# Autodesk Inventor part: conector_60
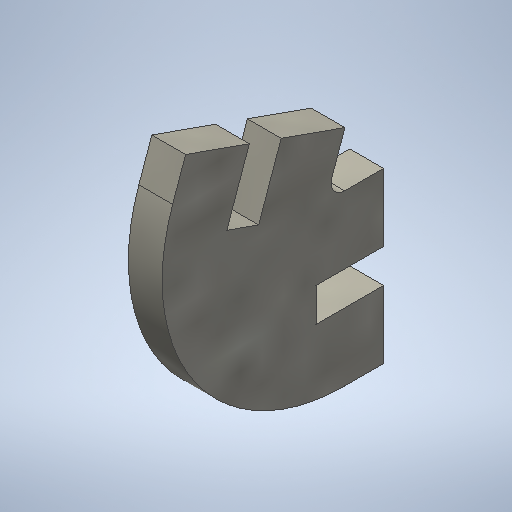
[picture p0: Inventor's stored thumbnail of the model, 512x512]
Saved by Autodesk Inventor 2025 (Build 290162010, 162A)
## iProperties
Created: 2025-02
Part Number: conector_60
Material: Paper
Document SubType Name: Modeling
Designer: BennF
Density: 0.93 g/cm^3
Appearance: Cardboard - Chipboard
Author: BennF
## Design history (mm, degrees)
sketch "Sketch2"
  geometry: L1 (0, -1)-(2.879, -1); L2 (2.879, -1)-(2.879, -6); L3 (2.879, -6)-(-2.121, -6); L4 (-2.121, -6)-(-2.121, -8.5); L5 (-2.121, -8.5)-(2.879, -8.5); L6 (2.879, -8.5)-(2.879, -13.5); L7 (2.879, -13.5)-(0, -13.5); L8 (-0.943, 0.333)-(0.017, 3.047); L9 (0.017, 3.047)-(-4.697, 4.714); L10 (-4.697, 4.714)-(-6.364, 0); L11 (-6.364, 0)-(-8.721, 0.833); L12 (-8.721, 0.833)-(-7.054, 5.547); L13 (-7.054, 5.547)-(-11.768, 7.214); L14 (-11.768, 7.214)-(-12.728, 4.5); L15 (-6.364, 0)-(-2.121, -6); A1 r 1 centre (0, 0) between (-0.943, 0.333) and (0, -1); A2 r 13.5 centre (0, 0) between (-12.728, 4.5) and (0, -13.5); 1 further point
  constraints: 30 end point, 10 perpendicular, 5 equal length, 4 point on circle, 4 point on line, 4 tangent, 2 centre point, 2 coincident, 1 horizontal
  dimensions: "d0" = 70.5288 deg angle of L1 L8 (= con_angle_3); "d1" = 2.5 distance of L10.end L11.end (= thickness); "d2" = 5 distance of L11.end L12.end (= slot_depth); "d3" = 5 distance of L12.end L13.end (= slot_dis_1); "d4" = 1 radius of A1; "d7" = 6 vertical distance of L3.end L10.end (computed from slot_depth)
extrude "Extrusion1" new body sketch "Sketch2" distance "d5" = 2.5 (= thickness); taper "d6" = 0 deg
sketch "laser"
  geometry: L1 (-4.714, -4.697)-(0, -6.364) reference; L2 (0, -6.364)-(-0.833, -8.721) reference; L3 (-0.833, -8.721)-(-5.547, -7.054) reference; L4 (-5.547, -7.054)-(-7.214, -11.768) reference; L5 (-7.214, -11.768)-(-4.5, -12.728) reference; L6 (13.5, 0)-(13.5, 2.879) reference; L7 (13.5, 2.879)-(8.5, 2.879) reference; L8 (8.5, 2.879)-(8.5, -2.121) reference; L9 (8.5, -2.121)-(6, -2.121) reference; L10 (6, -2.121)-(6, 2.879) reference; L11 (6, 2.879)-(1, 2.879) reference; L12 (1, 2.879)-(1, 0) reference; L13 (-0.333, -0.943)-(-3.047, 0.017) reference; L14 (-3.047, 0.017)-(-4.714, -4.697) reference; A1 r 13.5 centre (0, 0) between (-4.5, -12.728) and (13.5, 0) reference; A2 r 1 centre (0, 0) between (-0.333, -0.943) and (1, 0) reference; 1 further point
  node "Projected Loop1"
body "Solid1"
other parameters: "thickness" = 2.5 [user parameter; used in 2 equation terms], "clearence" = -0.5 [user parameter], "slot_depth" = 5 [user parameter; used in 2 equation terms], "slot_dis_1" = 5 [user parameter; used in 1 equation term], "slot_dis_2" = 12 [user parameter], "slot_clearenece" = 3 [user parameter], "con_angle_1" = 20.34444 [user parameter], "con_angle_2" = 60 deg [user parameter], "con_angle_3" = 70.5288 deg [user parameter; used in 1 equation term], "con_angle_4" = 19.10633 [user parameter], "con_angle_5" = 24.11865 [user parameter]
